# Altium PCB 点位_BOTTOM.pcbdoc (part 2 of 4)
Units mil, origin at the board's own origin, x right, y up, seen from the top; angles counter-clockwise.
Board outline 5102.8 x 4152 mil, 8 copper layers (Top Layer, GND1, 内层2, VCC, 内层4, Inner5, GND2, Bottom Layer); 209 components, 325 nets, 527 pads, 1119 vias.
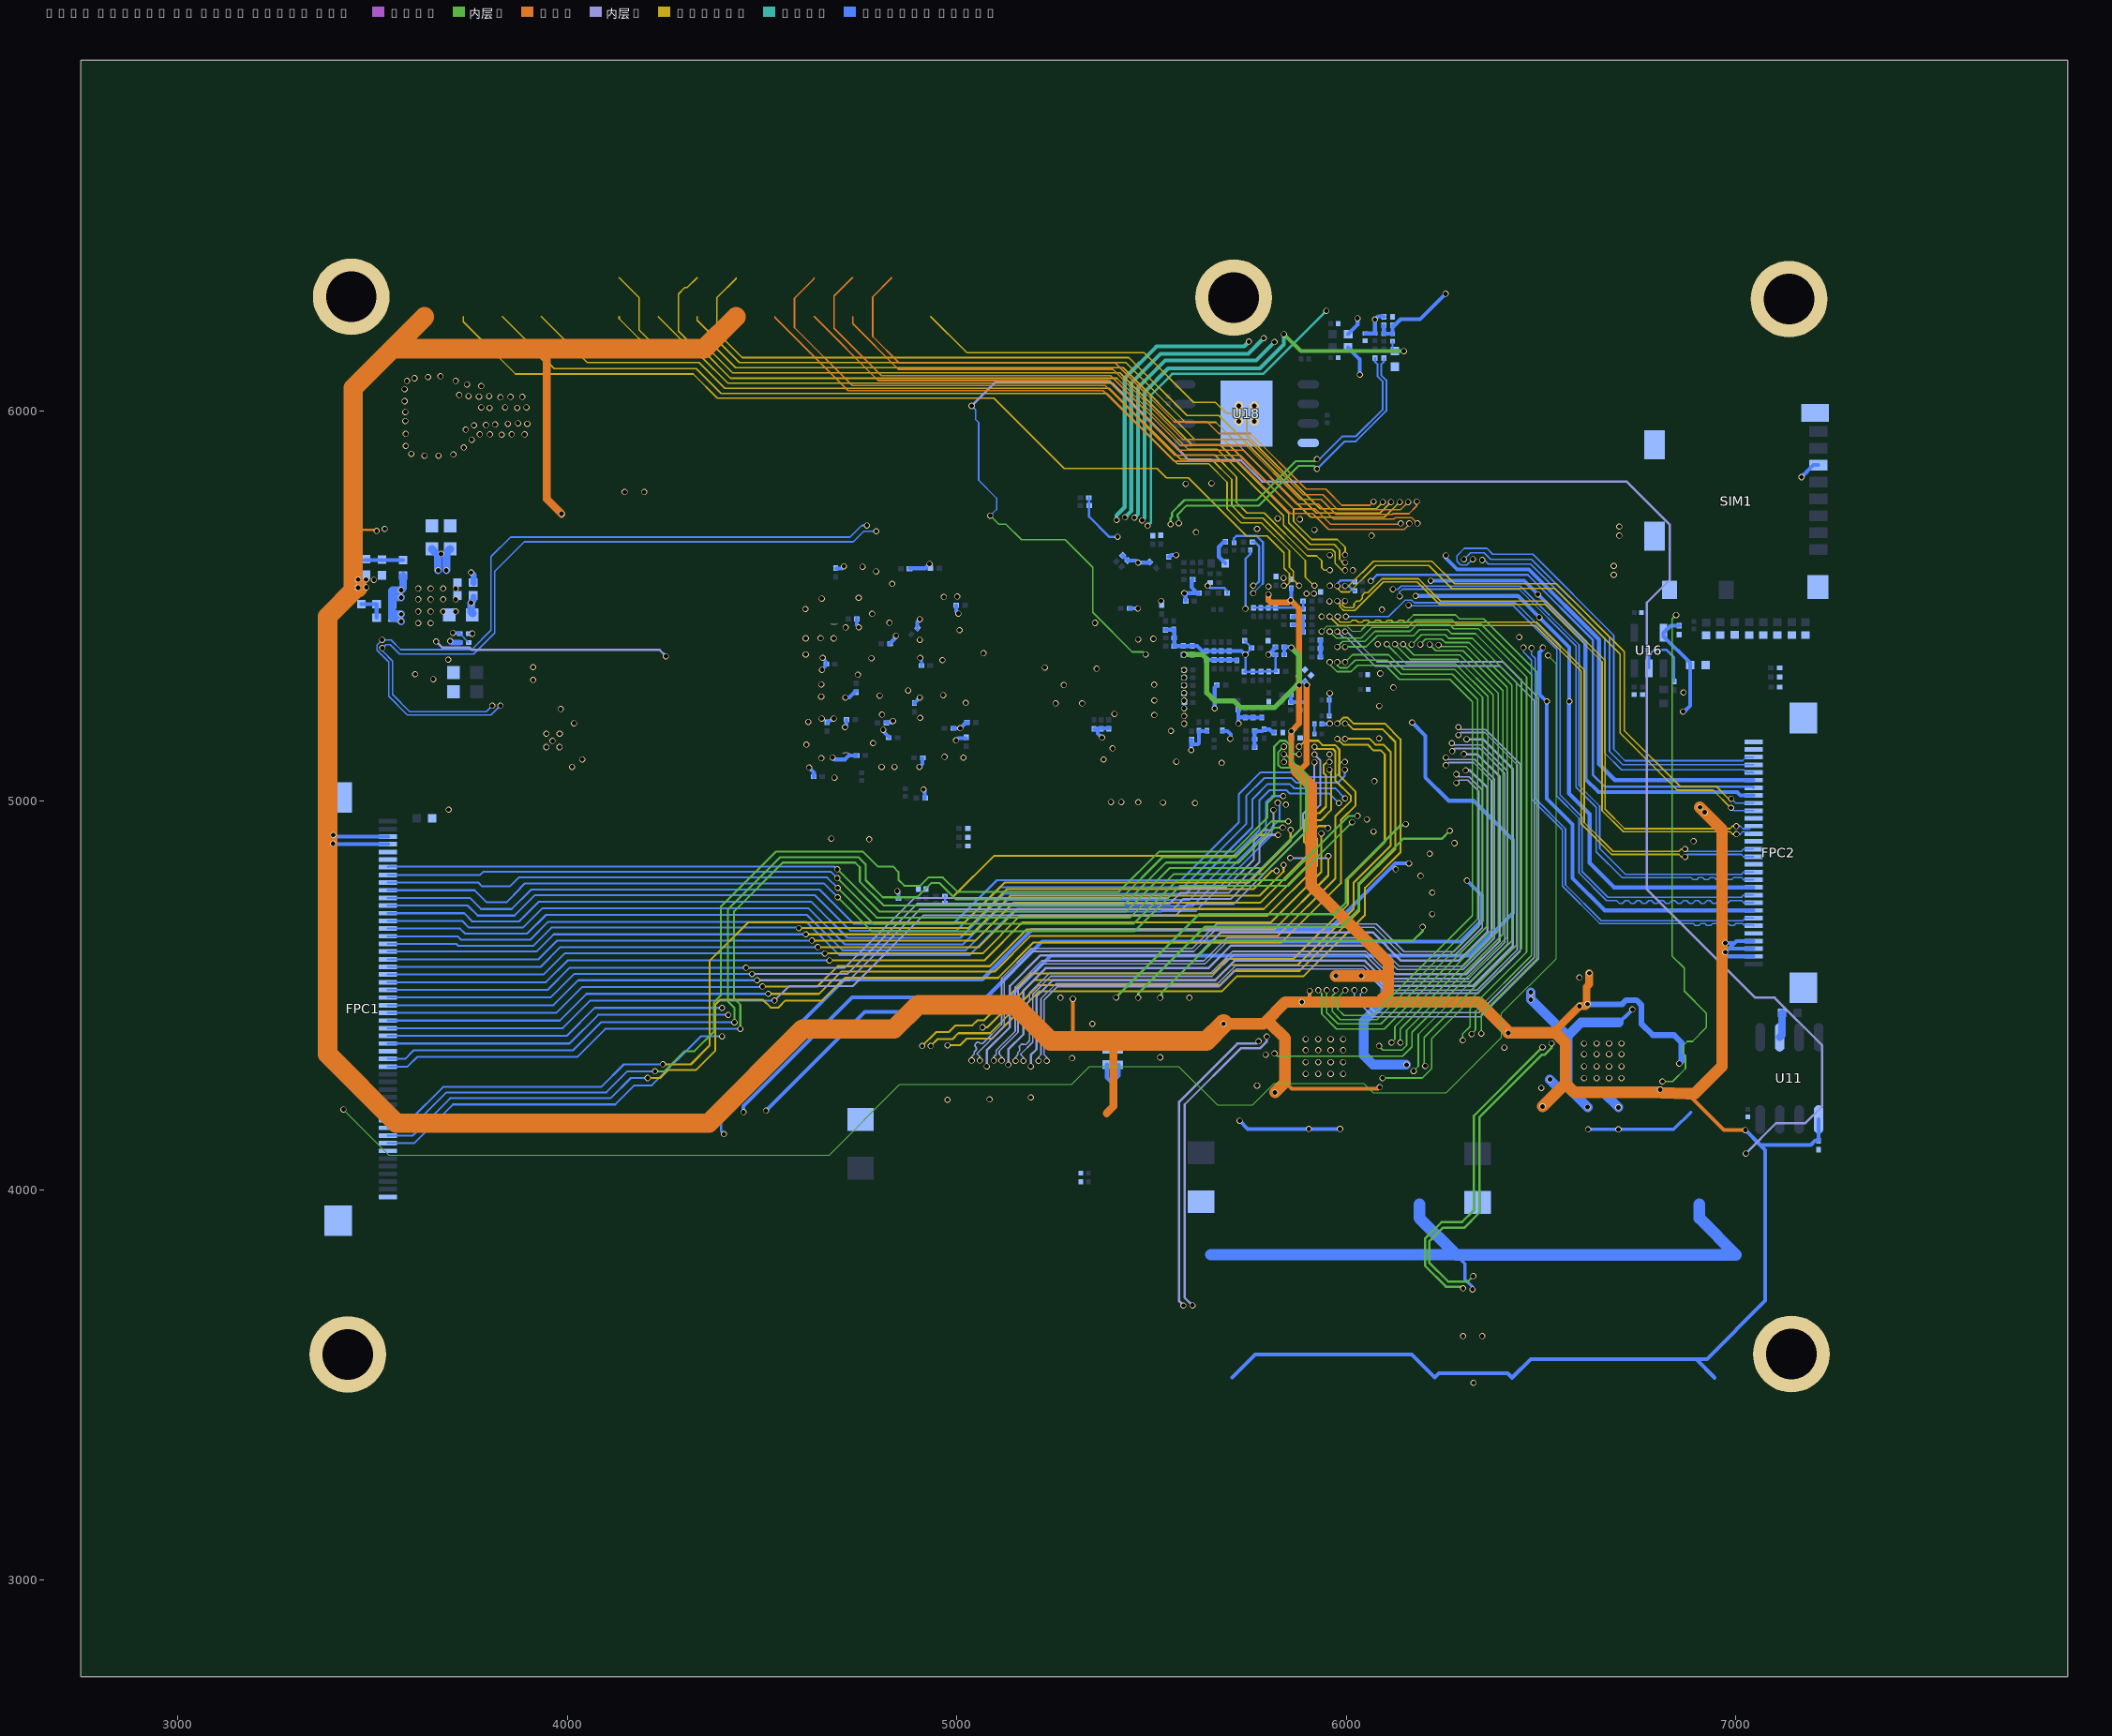
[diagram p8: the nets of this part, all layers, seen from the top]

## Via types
v1: diameter 15.75, hole 11.8, Top Layer to Bottom Layer, 496 vias
v2: diameter 15.7, hole 11.8, Top Layer to Bottom Layer, 335 vias
v3: diameter 15.75, hole 11.81, Top Layer to Bottom Layer, 279 vias
v4: diameter 24, hole 12, Top Layer to Bottom Layer, 9 vias

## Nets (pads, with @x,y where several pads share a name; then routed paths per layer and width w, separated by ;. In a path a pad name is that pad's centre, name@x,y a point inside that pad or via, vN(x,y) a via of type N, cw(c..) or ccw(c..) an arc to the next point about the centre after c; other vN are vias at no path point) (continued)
GM0_LED1:  | length 814.5
  内层4 w6: v2(5604.8,3703.92) 5584.8,3723.92 5584.8,4220 5728.8,4364 5777.8,4364 5795.8,4382 v2(5795.8,4394)
GM0_LED2:  | length 796.1
  内层4 w6: v2(5581.8,3703.69) 5570.8,3714.69 5570.8,4227 5719.8,4376 5768.8,4376 v2(5774.8,4382)
GM1_DVDD10:  | length 736.2
  Bottom Layer w10: 6699.8,4431 ccw(c6156.31,5042.49) v1(6734.8,4464)
  Bottom Layer w25: v1(6473.8,4508) v1(6473.8,4489.39) 6567.8,4395.39 ; v1(6522.8,4284) 6541.8,4265 6567.8,4265 ; v1(6619.8,4213) 6581.8,4251 ; v1(6698.8,4212.42) 6660.22,4251 6581.8,4251 ; 6699.8,4431 6603.41,4431 6567.8,4395.39 ; 6567.8,4265 6567.8,4395.39 ; 6567.8,4265 6581.8,4251
GM1_DVDDRG: C32.1 C34.1 C42.1 C167.2 C168.2 C169.2 C170.2 C173.2 C174.2 C175.2 C176.2 C177.2 C178.2 C200.2 C204.2 C223.2 C224.2 C276.1 FPC1.3 FPC1.4 FPC2.2 FPC2.3 FPC2.4 U11.5 U16.5 | length 15880.7
  内层2 w13: v2(5583.3,5375.16) 5630.64,5375.16 5641.8,5364 5641.8,5277 5662.8,5256 5711.8,5256 5728.8,5239 5814.8,5239 5872.8,5297 v2(5878.8,5297) 5878.8,5373 v2(5858.8,5393)
  VCC w6: 3449.8,5695.88 3506.92,5695.88 v1(3509.8,5693)
  VCC w10: 5297.42,4383 5297.8,4383.38 v2(5297.8,4491) ; 5842.8,4277 5859.8,4260 6081.8,4260 v2(6085.8,4264) ; 5905.69,4483 5905.8,4483.11 v2(5905.8,4511.5) ; v1(6805.8,4258) 6865.8,4258 6875.8,4248 6969.8,4154 v1(7024.8,4154)
  VCC w15: v1(5799.85,5529.95) 5799.85,5514.96 5805.8,5509 5850.8,5509 v2(5856.8,5515) 5878.8,5493 v2(5878.8,5297) 5878.8,5198.22 v1(5858.89,5178.3) 5858.8,5178.22 5858.8,5092 5867.8,5083 ; 5881.8,5079 5897.8,5095 5897.8,5296 v2(5898.8,5297)
  VCC w20: 3912.8,6165 3916.8,6161 3946.8,6131 3946.8,5774.7 v2(3984.8,5736.7) ; 5384.3,4197.4 5401.8,4214.9 5401.8,4379.05 5397.85,4383 ; 6531.1,4404 6531.1,4404.46 v1(6599.22,4472.58) 6614.4,4472.58 v1(6619.31,4477.49) 6616.8,4480 6616.8,4521.72 6623.8,4528.72 v2(6623.8,4557)
  VCC w30: v1(5684.8,4427) 5787.38,4427 5789.71,4429.34 ; v2(5816.8,4251) 5842.8,4277 5842.8,4390 5803.47,4429.34 5789.71,4429.34 ; 5870.8,5078 5909.43,5039.37 5909.43,4782.37 6107.8,4584 6107.8,4538.28 ; v2(5972.8,4550) v2(6038.15,4550) 6096.09,4550 6107.8,4538.28 ; 6092.8,4492 6107.8,4507 6107.8,4538.28 ; v1(6503.8,4215) 6562.8,4274 ; v1@6806.14,4251 6774.8,4251 ; v2(6907.8,4983) v2(6920.55,4970.25) 6964.8,4926 6964.8,4318 6894.8,4248 6875.8,4248 6774.8,4251 ; 5789.71,4429.34 5843.38,4483 v1(5885.8,4483) 5905.69,4483 6339.8,4483 6415.8,4407 v1(6415.8,4404) 6531.1,4404 6537.07,4404 6562.8,4378.26 6562.8,4274 ; 6562.8,4274 6585.8,4251 6774.8,4251
  VCC w50: 3449.8,5552 3449.8,5695.88 3449.8,6060 3550.8,6161 ; v1(3461.8,5547) 3457.84,5547 3383.8,5472.97 3383.8,4349 3560.8,4172 4362.36,4172 4604.36,4414 4838.8,4414 4900.8,4476 5147.8,4476 5240.8,4383 5297.42,4383 5397.85,4383 5640.8,4383 v1(5684.8,4427) ; 3632.8,6243 3550.8,6161 ; 4432.8,6243 4350.8,6161 3916.8,6161 3550.8,6161
  Bottom Layer w10: v2(3397.8,4890) 3399.58,4888.23 FPC1.4@3538.78,4888.23 ; v2(3398.8,4912) 3402.68,4908.12 3538.57,4908.12 FPC1.3@3538.78,4907.91 ; 5384.3,4197.4 5397.8,4210.9 5397.8,4276 ; C224.2@5384.9,4322.16 5384.9,4288.9 5397.8,4276 ; C223.2@5415.92,4322.1 5415.92,4294.11 5397.8,4276 ; 5706.8,3519.16 5765.65,3578 6167.96,3578 6226.8,3519.16 6237.65,3530 6414.2,3530 6425.8,3518.4 6473.4,3566 6898.2,3566 ; C174.2@5840.8,5375 C173.2@5840.8,5395 5856.8,5395 v2(5858.8,5393) ; v2(5856.8,5515) 5858.8,5517 C170.2@5858.8,5546 ; C169.2@5858.8,5161 5858.89,5161.09 v1(5858.89,5178.3) ; C175.2@5877.8,5276 5877.8,5296 v2(5878.8,5297) 5878.02,5297.78 C167.2@5878.02,5320.22 ; C168.2@5893.02,5306.22 5898.8,5300.44 v2(5898.8,5297) C176.2@5898.8,5276 ; C276.1@6854.8,5449.5 6833.06,5449.5 U16.5@6814.71,5431.15 6814.71,5422.09 6882.8,5354 6882.8,5244 6867.8,5229 v2(6864.8,5229) ; 6945.8,3518.4 6898.2,3566 ; v2(6972.8,4635) 6996.8,4635 ; v1(7024.8,4154) 7062.8,4116 ; FPC2.2@7045.83,4600.26 6979.55,4600.26 6970.8,4609 6981.74,4619.94 ; FPC2.3@7045.83,4619.94 6981.74,4619.94 ; FPC2.4@7045.83,4639.62 7001.43,4639.62 6996.8,4635 ; U11.5@7212.8,4181.39 C204.2@7212.8,4126.5 7203.3,4126.5 7192.8,4116 7062.8,4116 ; 6898.2,3566 6925.8,3566 7075.8,3716 7075.8,4103 7062.8,4116 ; 6981.74,4619.94 6996.8,4635
  Bottom Layer w13: C178.2@5581.18,5374.75 5581.44,5375 C177.2@5603.8,5375
  Bottom Layer w15: v1(6619.31,4477.49) 6619.8,4477 6707.8,4477 6718.8,4488 6744.8,4488 6757.8,4475 6757.8,4427 6786.8,4398 6841.8,4398 6860.8,4379 6860.8,4331 v1(6854.8,4325)
  Bottom Layer w25: v2(6038.15,4550) 6039.15,4551 6070.8,4551 ; 6074.8,4550 6099.8,4525 6099.8,4489 6044.8,4434 6044.8,4346 6068.8,4322 v1@6152.88,4322
  other v1: 6154.8,4322 3483.8,5548 3502.8,5567 3461.8,5568 3482.8,5568
  other v2: 6973.08,4611.28
GM1_LED1:  | length 868.4
  内层2 w6: v1(6325.8,3779) 6311.8,3765 6261.8,3765 6212.8,3814 6212.8,3867.95 6247.85,3903 6302.8,3903 6341.8,3942 6341.8,4187 6501.8,4347 6508.8,4347 6526.89,4365.09 v2(6526.89,4376.91)
GM1_LED2:  | length 838.6
  内层2 w6: v1(6299.8,3748) 6295.8,3752 6255.8,3752 6201.8,3806 6201.8,3875 6244.8,3918 6296.8,3918 6327.8,3949 6327.8,4191.02 v2(6503.78,4367)
GND: C13.2 C14.2 C19.2 C20.2 C21.2 C22.2 C23.2 C24.2 C26.2 C29.2 C30.2 C32.2 C34.2 C36.2 C37.2 C38.2 C39.2 C40.2 C41.2 C42.2 C46.2 C47.2 C48.2 C49.2 C50.2 C56.1 C57.2 C58.2 C67.2 C68.2 C75.2 C76.2 C77.2 C78.2 C79.1 C82.1 C83.2 C84.2 C85.2 C86.2 C90.1 C91.1 C92.1 C93.1 C94.1 C102.1 C103.1 C104.1 C105.1 C106.1 C107.1 C112.1 C113.1 C114.1 C115.1 C116.2 C117.2 C118.1 C119.1 C120.1 C121.1 C122.1 C123.1 C124.1 C125.1 C126.1 C127.1 C128.1 C129.1 C130.1 C132.2 C133.1 C134.2 C135.1 C137.1 C138.1 C141.1 C142.2 C143.2 C144.1 C145.1 C151.1 C152.1 C153.1 C154.1 C155.1 C156.1 C161.2 C162.1 C163.1 C164.1 C165.1 C166.1 C167.1 C168.1 C169.1 C170.1 C171.1 C172.1 C173.1 C174.1 C175.1 C176.1 C177.1 C178.1 C181.1 C182.1 C183.1 C184.1 C185.1 C186.1 C187.1 C188.1 C200.1 C201.1 C202.1 C204.1 C208.1 C209.1 C211.1 C213.1 C214.1 C215.1 C216.1 C223.1 C224.1 C225.2 C226.1 C227.1 C228.2 C229.1 C230.1 C231.2 C232.1 C233.1 C234.2 C235.1 C236.1 C237.1 C240.1 C246.1 C247.1 C248.1 C255.1 C276.2 C277.1 C285.1 C286.1 C287.1 C288.1 C289.1 C294.1 D16.2 D17.1 D18.2 D19.1 D20.2 D21.1 D22.2 D23.1 FPC1.5 FPC1.6 FPC1.31 FPC1.39 FPC1.44 FPC1.50 FPC1.51 FPC1.52 FPC2.5 FPC2.8 FPC2.11 FPC2.14 FPC2.17 FPC2.20 FPC2.23 FPC2.25 FPC2.29 FPC2.30 FPC2.31 FPC2.32 pad.54 R28.1 R44.1 R45.2 R46.1 R49.1 R55.1 R56.1 R57.1 R59.1 R67.1 R68.1 R76.2 R115.1 R116.2 R119.1 R122.1 SIM1.6 SIM1.9 SIM1.10 SIM1.12 SIM1.13 SIM1.14 U11.2 U16.2 U18.4 U18.9 | length 26839.9
  GND1 w3: 4676.72,5453.97 4678.72,5451.97 4690.72,5451.97 4692.72,5453.97 ; 4706.72,5121.97 4708.42,5121.97 4709.4,5122.95 4719.76,5122.95 4720.74,5121.97 4724.72,5121.97
  内层2 w6: v2(5408.8,4495) 5622.8,4709 5969.8,4709 5998.8,4738 5998.8,4797 6137.49,4935.68 6148.49,4935.68 v2(6152.8,4940) ; v2(5465.2,4493.87) 5465.2,4504.72 5636.48,4676 5985.8,4676 6031.8,4722 6031.8,4788 6145.8,4902 6244.8,4902 v2(6265.8,4923) ; v2(5521.8,4494) 5524.31,4494 5525.8,4495.49 5525.8,4507 5658.8,4640 6170.65,4640 6195.8,4665.15 v2(6195.8,4676)
  内层4 w6: v1(5076.8,4318) 5076.8,4359 5135.8,4418 5135.8,4524 5214.8,4603 5618.8,4603 5677.8,4662 6067.8,4662 6140.8,4589 6287.8,4589 6361.8,4663 6361.8,5033.87 6317.68,5078 v1(6306.8,5078) ; v2(5131.8,4322) 5131.8,4361 5170.8,4400 5170.8,4513 5227.8,4570 5645.8,4570 5703.8,4628 6051.8,4628 6124.8,4555 6308.8,4555 6393.8,4640 6393.8,5062 6336.8,5119 6302.8,5119 v1(6301.8,5120) ; v1(5189.8,4318) 5189.8,4347 5204.8,4362 5204.8,4498 5245.8,4539 5662.8,4539 5712.8,4589 6047.8,4589 6112.8,4524 6324.8,4524 6426.8,4626 6426.8,5082 6350.8,5158 v1(6308.8,5158)
  Bottom Layer w4: C46.2@3723.8,5429 C30.2@3745.8,5406
  Bottom Layer w6: 4398.8,4229 4394.8,4225 4394.8,4151 v2(4401.8,4144) ; C225.2@4968.8,4736 4969.3,4736.5 C226.1@4969.3,4755 ; C184.1@5339.27,5778.12 5339.58,5777.81 C183.1@5339.58,5758.12 5339.58,5729.23 5390.8,5678 v1(5412.8,5678) ; v2(5643.8,5552) 5649.8,5546 5686.8,5546 5694.3,5538.5 C112.1@5694.3,5533 ; C208.1@5738.8,5411.5 5756.8,5393.5 C47.2@5756.8,5392 5756.8,5391.18 v2(5740.78,5375.16) 5740.78,5333.98 C19.2@5737.8,5331 C24.2@5759.8,5331 5779.8,5331 C50.2@5780.8,5332 C49.2@5800.8,5332 C187.1@5816.96,5332 ; C107.1@5758.3,5664 5765.8,5664 5775.8,5654 5775.8,5563 5765.12,5552.31 v1(5760.88,5552.31) ; C77.2@5761.55,5495.75 C78.2@5780.55,5495.75 C76.2@5799.55,5495.75 C75.2@5818.55,5495.75 5885.55,5495.75 C211.1@5889.3,5492 C213.1@5889.3,5513 ; C174.1@5818.3,5375 5818.3,5333.34 C187.1@5816.96,5332 ; C187.1@5821.3,5332 C187.1@5816.96,5332 ; R55.1@5918.29,5171.53 R59.1@5918.29,5197 ; R46.1@5956.31,5218 R44.1@5956.31,5258.47 5957.33,5259.48 v1(5957.33,5276) ; U16.2@6777.31,5340.31 6777.31,5374.51 6790.8,5388 6821.8,5388 6841.8,5368 C277.1@6841.8,5306.5
  Bottom Layer w8: v2(3705.8,5431) 3721.8,5431 C46.2@3723.8,5429 ; v3(4653.64,5335.97) 4664.22,5346.55 4664.22,5357.89 v3(4655.12,5366.99) ; v3(4905.59,5366.86) 4909.22,5363.23 C121.1@4909.22,5345.97 ; 6282.56,3833.5 6304.8,3811.26 6304.8,3771 6323.8,3752 v1(6323.8,3745) ; v1(6620.8,4156) v1(6698.8,4156) 6840.8,4156 6884.8,4200
  Bottom Layer w10: C42.2@3470.8,5504.99 3509.53,5504.99 C29.2@3509.81,5504.72 C79.1@3509.81,5470 ; C34.2@3479.01,5618.33 3479.33,5618.01 3511.8,5618.01 3542.8,5618.01 C26.2@3577.8,5618.01 ; 4398.8,4229 4710.8,4541 5064.8,4541 5191.8,4668 5954.8,4668 6125.8,4839 v1(6160.8,4839) ; v2@4451.8,4204 4451.8,4216 4730.8,4495 5075.8,4495 5218.8,4638 6293.8,4638 6348.8,4693 6348.8,4756 v2(6309.8,4795) ; v2(4509.8,4204) 4763.8,4458 5096.8,4458 5240.8,4602 6317.8,4602 6427.8,4712 6427.8,4899 6326.8,5000 6262.8,5000 6202.8,5060 6202.8,5167 v2(6168.8,5201) ; v3(4620.57,5084.95) 4632.62,5072.9 C116.2@4632.62,5060.67 ; C117.2@4666.8,5201 v3(4683.78,5211.02) ; v3(4680.72,5110.97) 4685.72,5105.97 4712.72,5105.97 4722.72,5115.97 C124.1@4742.88,5115.97 ; C143.2@4689.72,5596.47 4704.22,5596.47 v3(4709.72,5601.97) ; v3(4712.72,5188.97) 4716.22,5192.47 C137.1@4716.22,5207.97 ; v3(4713.71,5265.01) 4723.75,5265.01 4739.87,5281.13 C142.2@4741.72,5281.13 ; C130.1@4742.6,5467.31 4742.6,5450.77 v3(4748.05,5445.32) ; v3(4810.72,5181.97) 4810.72,5178.47 C135.1@4826.22,5162.97 ; C151.1@4817.56,5200.97 4831.64,5200.97 v3(4835.64,5204.97) ; C120.1@4826.6,5402.68 4843.9,5419.98 v3(4843.9,5423.94) ; v2(4846.8,4768) 4850.3,4764.5 C230.1@4850.3,4749 ; C144.1@4877.56,5596.97 4918.72,5596.97 v3(4929.72,5607.97) ; C134.2@4891.72,5249.81 4891.72,5251.97 v3(4904.72,5264.97) ; C141.1@4897.88,5440.97 4897.88,5459.13 v3(4904.72,5465.97) ; v3(4903.72,5086.97) 4911.22,5094.47 C118.1@4911.22,5109.97 ; v3(4914.08,5028.72) 4917.74,5025.06 4917.74,5007.06 C152.1@4916.74,5006.06 ; C138.1@4990.22,5186.97 4991.22,5185.97 v3(5008.72,5185.97) 5023.72,5200.97 C122.1@5027.88,5200.97 ; C145.1@4997.88,5500.97 4997.88,5486.33 v3(5003.72,5480.49) ; v3(4998.02,5154.7) 5004.13,5160.81 C123.1@5022.72,5160.81 ; C162.1@5353.72,5183.97 5355.57,5183.97 5361.72,5177.83 ; v3(5372.72,5161.97) 5361.72,5172.97 5361.72,5177.83 ; C132.2@5391.72,5187.13 5390.72,5186.13 5361.72,5186.13 5361.72,5177.83 ; C181.1@5425.29,5630.17 C182.1@5438.73,5616.74 5459.83,5616.74 v2(5465.2,5611.37) 5493.91,5611.37 C202.1@5495.67,5613.13 ; C94.1@5443.3,5494 v2(5464.8,5494) ; C13.2@5535.45,5439.18 5556.32,5439.18 C14.2@5556.49,5439.35 5558.3,5437.54 C90.1@5558.3,5418 C93.1@5558.3,5397 5600.68,5397 5601.06,5397.38 5617.08,5397.38 5629.65,5384.81 C84.2@5641.03,5384.81 C83.2@5660.03,5384.81 C86.2@5699.03,5384.81 5731.13,5384.81 v2(5740.78,5375.16) ; C172.1@5543.8,5626.5 5545.45,5626.5 5549.95,5631 v2(5562.8,5631) ; C102.1@5587.3,5513 5587.3,5529.5 v2(5583.8,5533) C113.1@5617.8,5533 ; v3(5601.72,5129.97) 5601.72,5142.47 ; C133.1@5602.8,5156.5 5601.72,5155.42 5601.72,5142.47 ; C103.1@5605.3,5568 5602.8,5565.5 5602.8,5548 C113.1@5617.8,5533 ; C113.1@5621.3,5533 C113.1@5617.8,5533 ; C40.2@5640.8,5362 5717.88,5362 C39.2@5718.91,5360.97 ; C119.1@5642.72,5178.47 5621.72,5178.47 5621.72,5147.97 5618.72,5144.97 5604.22,5144.97 5601.72,5142.47 ; v2(5661.8,5237) 5661.8,5291 C41.2@5667.8,5297 ; C129.1@5681.72,5178.47 5695.22,5178.47 5703.72,5169.97 5703.72,5160.97 v3(5701.72,5158.97) ; R28.1@5688.8,5610 5672.8,5626 5672.8,5652 5685.3,5664.5 C106.1@5689.8,5664.5 ; C20.2@5721.8,5234 5722.8,5233 5722.8,5214.13 ; v2(5722.8,5198) 5722.8,5214.13 ; v1(5725.8,4178) 5746.8,4157 v1(5903.8,4157) v1(5983.8,4157) ; C227.1@5764.3,5137 C163.1@5764.3,5158 C164.1@5764.3,5179 5784.3,5179 C91.1@5788.8,5183.5 5789.5,5182.8 5803.64,5182.8 5810.95,5175.5 C166.1@5814.8,5175.5 ; C21.2@5782.8,5214 C22.2@5760.8,5214 5760.67,5214.13 5722.8,5214.13 ; C174.1@5818.3,5375 5818.15,5375.16 v2(5799.84,5375.16) 5818.3,5393.62 C173.1@5818.3,5395 ; C186.1@5857.3,5272 C185.1@5857.3,5253 C175.1@5878.3,5253 ; C104.1@5862.3,5452 C215.1@5888.8,5452 ; C188.1@5862.3,5473 5887.8,5473 C216.1@5888.8,5472 C215.1@5888.8,5452 ; C175.1@5877.8,5253.5 C175.1@5878.3,5253 ; C201.1@5880.3,5233 5880.3,5251 C175.1@5878.3,5253 ; C68.2@5888.8,5433 C215.1@5888.8,5452 ; C176.1@5898.8,5253.5 5898.3,5253 C175.1@5878.3,5253 ; C58.2@5933.8,5369 C57.2@5933.8,5391 C67.2@5933.8,5413 ; v2(6177.8,5526) 6440.8,5526 v2(6495.8,5471) 6572.8,5394 v2(6572.8,5255) 6571.8,5254 6571.8,5019 6624.8,4966 6624.8,4840 6687.39,4777.41 FPC2.11@7045.83,4777.41 ; v2(6216.8,5565) 6456.8,5565 v2(6491.8,5530) 6613.8,5408 6613.8,5056 6647.8,5022 7003.8,5022 7012.17,5013.64 FPC2.23@7045.83,5013.64 ; v2(6255.8,5630) 6255.8,5623 6284.8,5594 6468.8,5594 6648.8,5414 6648.8,5094 6689.8,5053.01 FPC2.25@7045.83,5053.01 ; v2(6504.8,5393) 6504.8,5390 6495.8,5381 6495.8,5274 v2(6514.8,5255) 6514.8,5005 6580.8,4939 6580.8,4801 6663.44,4718.36 FPC2.8@7045.83,4718.36 ; v1(7168.8,5831) 7199.82,5862.02 SIM1.6@7211.94,5862.02
  Bottom Layer w20: U11.2@7112.8,4392.61 7118.8,4398.6 C246.1@7118.8,4455.28
  Bottom Layer w30: 5651.8,3834.26 6281.8,3834.26 ; 6187.7,3964.16 6187.7,3928.36 6281.8,3834.26 ; 6906.7,3963.4 6906.7,3927.6 7000.8,3833.5 6282.56,3833.5 6281.8,3834.26
  other v1: 6326.8,3505 6299.8,3625 6348.8,3625 5083.8,4233 5189.8,4238 5295.81,4339 5521.8,4341 5521.8,4341 5792.8,4348 5347.8,4427 5844.8,4990 6071.8,5050 5839.52,5099.56 5956.8,5119 3945.89,5137.74 3979.71,5137.74 3961.64,5153.49 6083.8,5160 3945.8,5172 3979.8,5172 5583.3,5197.99 5583.3,5217.68 5583.3,5237.36 6084.68,5243.47 5583.3,5257.03 5583.3,5276.73 6120.8,5291 5583.3,5296.4 3655.09,5312 5583.3,5316.1 3608.8,5325 6087.22,5326.69 5583.3,5335.78 3693.55,5362.22 6080.8,5402 5465.2,5414.53 5504.56,5415.76 5354.8,5456.76 6091.55,5490.65 5799.8,5550 5957.8,5552 5838.8,5572 6686.8,5580 6016.8,5592 6686.8,5603 5957.8,5631 6064.8,5681 6700.8,5681 5614.23,5689.43 5917.8,5696 5770.8,5698 6700.8,5704 5880.45,5722.74 5823.8,5725 5587.8,5814 5653.8,5815
  other v2: 4451.8,4200.58 4975.8,4232 6500.8,4262.5 5770.8,4268.47 6610.71,4287.95 6642.71,4287.95 6674.71,4287.95 6706.71,4287.95 5895.8,4298.5 5927.8,4298.5 5959.8,4298.5 5991.8,4298.5 6610.71,4317.95 6642.71,4317.95 6674.71,4317.95 6706.71,4317.95 5895.8,4328.5 5927.8,4328.5 5959.8,4328.5 5991.8,4328.5 6610.71,4348.95 6642.71,4348.95 6674.71,4348.95 6706.71,4348.95 5895.8,4359.5 5927.8,4359.5 5959.8,4359.5 5991.8,4359.5 6405.8,4366 6610.71,4376.95 6642.71,4376.95 6674.71,4376.95 6706.71,4376.95 5895.8,4387.5 5927.8,4387.5 5959.8,4387.5 5991.8,4387.5 5265.8,4494 5596.8,4494 6598.8,4546 6220.8,4709 6220.8,4764 6190.8,4807 6126.8,4824 6213.8,4864 6277.8,4891 6891.8,4896 4774.8,4901 4677.8,4903 6069.8,4921 6052.8,4952 3694.8,4977 4011.8,5087 6865.8,5278 3911.8,5310.28 3911.8,5343 6443.8,5420 3616.8,5456 3648.8,5456 5936.8,5473 3616.8,5486 3648.8,5486 3680.8,5486 3712.8,5486 5956.8,5512 5524.25,5512.95 3616.8,5517 3648.8,5517 3680.8,5517 3712.8,5517 5897.8,5532 5916.8,5532 3616.8,5545 3648.8,5545 3680.8,5545 3712.8,5545 3530.8,5698 4146.85,5793 4196.8,5793 3632.8,5886 3668.8,5886 3706.8,5889 3598.8,5891 3733.8,5907 3584.8,5911 3753.8,5927 3830.8,5940 3774.8,5941 3800.8,5941 3856.8,5941 3889.8,5941 3584.8,5942 3738.8,5953 3759.8,5964 3790.8,5965 3813.8,5966 3846.8,5968 3896.8,5968 3872.8,5969 3583.8,5975 3583.8,5998 3799.8,6009 3870.8,6009 3778.8,6010 3839.8,6010 3894.8,6010 3581.8,6026 3827.8,6036 3853.8,6037 3883.8,6037 3772.8,6038 3745.8,6039 3798.8,6039 3721.8,6042 3581.8,6057 3778.8,6065 3741.8,6069 3587.8,6078 3712.8,6078 3606.8,6085 3641.8,6088 3673.8,6090
  other v3: 5611.72,4993.97 5465.72,4995.97 5529.24,4995.51 5395.41,4996.51 5421.96,4996.51 4685.37,5059.21 4806.72,5086.97 4839.72,5086.97 5680.01,5097.25 5563.72,5099.97 5376.72,5105.97 4651.72,5108.97 5016.72,5110.64 4968.09,5112.71 5399.97,5134.47 4613.64,5143.97 4784.72,5147.97 5549.72,5179.22 4618.33,5202.59 4653.07,5210.76 4905.72,5212.97 5506.8,5220 4807.72,5220.97 5404.72,5222.97 5253.72,5249.97 5321.72,5249.97 5022.72,5251.22 5506.77,5257.46 4651.48,5267.64 4801.72,5269.97 4964.8,5271 4874.72,5282.97 5274.72,5296.72 5506.56,5298.24 4651.64,5298.97 4745.71,5323.56 5358.8,5339 5225.72,5341.97 4962.72,5360.97 4780.72,5365.97 4611.72,5375.97 5068.3,5378.72 4904.72,5413.15 4611.72,5416.97 4650.01,5417.22 4683.72,5416.97 5006.8,5438.05 4714.52,5444.96 4826.72,5456.97 4782.2,5479.83 4610.67,5492.24 4653.1,5519.11 4747.72,5521.01 4966.64,5522.97 5000.98,5524.33 4833.72,5556.97 4792.72,5588.97 4757.72,5600.97
  other v4: 5724.12,5974.31 5763.49,5974.31 5724.12,6013.68 5763.49,6013.68
HBIAS: C237.2 R64.2 | length 1143.7
  内层2 w10: v1(5839.8,6198) 5883.31,6154.49 v1(6147.8,6154.49)
  GND2 w10: v1(5475.8,5720) 5481.8,5726 5481.8,6049 5542.8,6110 5777.8,6110 5839.8,6172 v1(5839.8,6198)
  Bottom Layer w5: R64.2@6118.57,6179.98 6118.57,6160.49 C237.2@6124.57,6154.49 v1(6147.8,6154.49)
HCEC:  | length 1807
  Inner5 w5: v1(4910.8,4370) 4946.8,4406 4979.8,4406 4996.8,4423 5039.8,4423 5052.8,4436 5069.8,4436 5189.8,4556 5656.8,4556 5694.8,4594 5864.8,4594 6003.8,4733 6003.8,4798 6098.8,4893 6098.8,5119 6088.8,5129 6069.8,5129 6054.8,5144 5991.94,5144 v1(5977.01,5158.93)
HHPD:  | length 1652.4
  Inner5 w5: v1(5065.8,4418) 5077.8,4418 5199.8,4540 5664.8,4540 5702.8,4578 5874.8,4578 6018.8,4722 6018.8,4789 6113.8,4884 6113.8,5125 6094.8,5144 6074.8,5144 6059.87,5158.93 v1(5996.69,5158.93)
HP-DET:  | length 879.2
  GND2 w6: v1(5489.8,5706) 5497.8,5714 5497.8,6041 5552.8,6096 5786.8,6096 v1(5948.8,6258)
HPOUTFB: C239.1 R66.2 R122.2 | length 826.9
  GND2 w10: v1(5431.8,5728) 5447.8,5744 5447.8,6073 5522.8,6148 5747.8,6148 v1(5787.8,6188)
  Bottom Layer w10: R122.2@6048.57,6200 R66.2@6073.57,6200 v1(6073.57,6235.76) 6081.8,6244 6095.55,6244 C239.1@6096.57,6242.99
HPOUTL: C243.1 | length 788.1
  GND2 w10: v1(5455.8,5727) 5464.8,5736 5464.8,6061 5534.8,6131 5768.8,6131 v1(5815.8,6178)
  Bottom Layer w10: C243.1@6004.8,6198 6028.8,6222.01 v1(6028.8,6239)
HPOUTR: C242.1 | length 813
  GND2 w10: v1(5409.8,5721) 5409.8,5733 5430.8,5754 5430.8,6085 5512.8,6167 5737.8,6167 v1(5749.8,6179)
  Bottom Layer w10: C242.1@6004.52,6163.85 6034.8,6133.57 v1(6034.8,6094)
HREXT: R59.2 | length 20.6
  Bottom Layer w10: R59.2@5937.31,5197 5956.03,5197 v1(5957.33,5198.3)
HS-MIC: C239.2 C240.2 R64.1 R65.2 | length 235.1
  Bottom Layer w5: R65.2@6096.57,6199.49 R65.2@6096.99,6199.06
  Bottom Layer w10: R65.2@6096.57,6199 6096.57,6199.49 C239.2@6096.57,6220.49 ; R65.2@6096.99,6199.06 R64.1@6118.5,6199.06 ; R64.1@6118.57,6199 C240.2@6118.57,6220.49 6123.29,6220.49 6139.8,6237 6189.8,6237 v1(6254.8,6302)
HSCL:  | length 1865.5
  Inner5 w5: v1(4932.8,4370) 4950.8,4388 4988.8,4388 5003.8,4403 5085.8,4403 5208.8,4526 5673.8,4526 5710.8,4563 5879.8,4563 6032.8,4716 6032.8,4783 6125.8,4876 6125.8,5151 6093.8,5183 6017.8,5183 6002.5,5198.3 v1(5996.69,5198.3)
HSDA:  | length 1891
  Inner5 w5: v1(4975.8,4372) 5007.8,4372 5024.8,4389 5089.8,4389 5211.8,4511 5680.8,4511 5718.8,4549 5889.8,4549 6047.8,4707 6047.8,4776 6138.8,4867 6138.8,5158 6098.51,5198.3 6018.51,5198.3 6002.8,5214 5992.7,5214 v1(5977,5198.3)
HTX0N:  | length 2088.5
  内层4 w4: v1(5094.8,4333) 5094.8,4342.87 5100.8,4348.87 5100.8,4358.99 5149.8,4408 5149.8,4521.34 5217.48,4589.02 5633.82,4589.02 5692.82,4648.02 6062.79,4648.02 6136.14,4574.67 6296.47,4574.67 6372.8,4651 6372.8,5052 6326.8,5098 6262.8,5098 v1(6255.8,5091)
HTX0P:  | length 2101
  内层4 w4: v1(5114.8,4333) 5114.8,4342.87 5108.81,4348.87 5108.81,4357.11 5156.8,4405.1 5156.8,4517 5220.8,4581 5637.14,4581 5696.14,4640 6057.8,4640 6131.15,4566.65 6299.79,4566.65 6380.8,4647.66 6380.8,5055.34 6330.12,5106.02 6260.79,5106.02 v1(6255.8,5111)
HTX1N:  | length 2140
  内层4 w4: v1(5150.8,4332) 5150.8,4341.87 5156.3,4347.37 5156.3,4353.02 5161.07,4357.8 5161.07,4363.46 5160.49,4364.03 5160.49,4369.69 5165.44,4374.64 5171.1,4374.64 5171.68,4374.06 5177.33,4374.06 5186.79,4383.52 5186.79,4406.66 5181.79,4411.66 5181.79,4421.66 5186.79,4426.66 5186.79,4436.66 5181.79,4441.66 5181.79,4451.66 5186.79,4456.66 5186.79,4466.66 5181.79,4471.66 5181.79,4481.66 5186.79,4486.66 5186.79,4506.32 5237.48,4557.02 5651.82,4557.02 5707.8,4613 6050.79,4613.02 6120.8,4543 6313.8,4543 6406.8,4636 6406.8,5070 6342.8,5134 6278.8,5134 v1(6271.8,5127)
HTX1P:  | length 2133.8
  内层4 w4: v1(5170.8,4332) 5170.8,4340.87 5164.31,4347.37 5164.31,4349.37 5194.8,4379.86 5194.8,4503 5240.8,4549 5655.14,4549 5711.14,4605 6046.8,4605 6116.82,4534.98 6317.12,4534.98 6413.8,4631.66 6413.8,5076 6346.8,5143 6275.8,5143 v1(6270.8,5148)
HTX2N:  | length 2151.2
  内层4 w4: v1(5209.8,4332) 5209.8,4341.87 5216.13,4348.2 5216.13,4491.66 5254.48,4530.02 5669.48,4530.02 5715.47,4576 ; 5715.48,4576.02 6046.1,4576.02 6108.12,4514 6335.8,4514 6438.8,4617 6438.8,5092.1 6355.9,5175 6293.8,5175 v1(6287.8,5169)
HTX2P:  | length 2163.6
  内层4 w4: v1(5230.47,4332) 5230.47,4341.87 5224.14,4348.2 5224.14,4488.34 5257.8,4522 5672.8,4522 5718.8,4568 6042.8,4568 6104.82,4505.98 6339.12,4505.98 6446.82,4613.68 6446.82,5093.98 6357.8,5183 6293.8,5183 v1(6287.8,5189)
HTXCN:  | length 2017.3
  内层4 w4: v1(5037.8,4333) 5037.8,4342.87 5044.3,4349.37 5044.3,4354.69 5048.16,4358.56 ccw(c5043.71,4363.01) 5048.16,4367.46 cw(c5052.62,4371.91) 5048.16,4376.36 5049.87,4378.07 cw(c5054.32,4373.61) 5058.77,4378.07 ccw(c5063.22,4382.52) 5067.67,4378.07 5114.8,4425.19 5114.8,4544.34 5191.48,4621.02 5604.82,4621.02 5666.82,4683.02 6076.79,4683.02 6147.8,4612 6275.8,4612 6340.8,4677 6340.8,5024 6311.8,5053 6289.8,5053 v1(6282.8,5046)
HTXCP:  | length 2016.2
  内层4 w4: v1(5058.8,4333) 5058.8,4342.87 5052.31,4349.37 5052.31,4351.37 5121.8,4420.86 5121.8,4540 5194.8,4613 5608.14,4613 5670.14,4675 6071.8,4675 6142.82,4603.98 6279.12,4603.98 6348.82,4673.68 6348.82,5027.32 6315.14,5061 6289.8,5061 v1(6282.8,5068)
IR-RX:  | length 4880.4
  内层2 w4: v2(5085.8,5732) 5107.8,5710 5125.8,5710 5165.8,5670 5277.8,5670 5348.8,5599 5348.8,5483.58 5450.38,5382 5478.8,5382 v2(5484.8,5376)
  内层4 w6: v2(5037.8,6014) 5100.8,6077 5392.8,6077 5594.8,5875 5728.8,5875 5783.8,5820 6718.8,5820 6830.8,5708 6830.8,5568 6771.8,5509 6771.8,4772 7049.8,4494 7099.8,4494 7221.8,4372 7221.8,4215 7178.8,4172 7103.8,4172 v2(7025.8,4094)
  Bottom Layer w4: v2(5037.8,6014) 5047.8,6004 5047.8,5979 5055.8,5971 5055.8,5823 5101.8,5777 5101.8,5748 v2(5085.8,5732)
LCD0-CLK: FPC1.43 | length 971.7
  Bottom Layer w5: FPC1.43@3538.78,4120.52 3606.32,4120.52 3705.8,4220 4122.8,4220 4171.8,4269 4216.8,4269 4342.8,4395 v1(4396.8,4395)
LCD0-D0: FPC1.7 | length 2737.5
  内层2 w5: v1(4692.8,4824) 4801.8,4715 5433.8,4715 5545.8,4827 5781.8,4827 5882.8,4928 5882.8,5060 5857.8,5085 5831.8,5085 5824.8,5092 5824.8,5124.22 v1(5839.52,5138.93)
  Bottom Layer w5: FPC1.7@3538.78,4829.18 3540.78,4831.18 4685.63,4831.18 v1(4692.8,4824)
LCD0-D1: FPC1.8 | length 2726.6
  内层2 w5: v1(4692.8,4801) 4793.8,4700 5444.8,4700 5556.8,4812 5786.8,4812 5897.8,4923 5897.8,5065 5843.56,5119.25 v1(5839.52,5119.25)
  Bottom Layer w5: FPC1.8@3538.78,4809.48 3775.48,4809.48 3784,4818 4675.8,4818 v1(4692.8,4801)
LCD0-D2: FPC1.9 | length 2667.6
  内层2 w5: v1(4693.8,4776) 4785.8,4684 5453.8,4684 5565.8,4796 5841.8,4796 6006.8,4961 v1(6028.8,4961)
  Bottom Layer w5: FPC1.9@3538.78,4789.81 3771,4789.81 3780.8,4780 3851.8,4780 3874.8,4803 4666.8,4803 v1(4693.8,4776)
LCD0-D3: FPC1.10 | length 2676.7
  内层2 w5: v1(4693.8,4752) 4780.8,4665 5456.8,4665 5572.8,4781 5850.8,4781 v1(6014.8,4945)
  Bottom Layer w5: FPC1.10@3538.78,4770.11 3761.69,4770.11 3792.8,4739 3842.8,4739 3878.8,4775 3878.8,4776 3890.8,4788 4657.8,4788 v1(4693.8,4752)
LCD0-D4: FPC1.11 | length 2763.8
  Bottom Layer w5: FPC1.11@3538.78,4750.44 3749.37,4750.44 3777.8,4722 3856.8,4722 3906.8,4772 4646.8,4772 4734.8,4684 4990.8,4684 5102.8,4796 5574.8,4796 5723.8,4945 5723.8,5017 5779.8,5073 5864.8,5073 5876.8,5061 5972.12,5061 5981.8,5070.68 5981.8,5093.57 5987.79,5099.56 v1(5996.01,5099.56)
LCD0-D5: FPC1.12 | length 2759.9
  Bottom Layer w5: FPC1.12@3538.78,4730.74 3744.06,4730.74 3769.8,4705 3863.8,4705 3915.8,4757 4635.8,4757 4726.8,4666 4998.8,4666 5110.8,4778 5580.8,4778 5742.8,4940 5742.8,5012 5788.8,5058 5859.8,5058 5871.8,5046 5977.8,5046 5996,5064.2 v1(5996,5079.88)
LCD0-D6: FPC1.13 | length 2747.5
  Bottom Layer w5: FPC1.13@3538.78,4711.06 3734.74,4711.06 3755.8,4690 3875.8,4690 3926.8,4741 4625.8,4741 4718.8,4648 5008.8,4648 5121.8,4761 5587.8,4761 5758.8,4932 5758.8,5004 5797.8,5043 5854.8,5043 5865.8,5032 5970.8,5032 v1(5996.8,5006)
LCD0-D7: FPC1.14 | length 2730.7
  Bottom Layer w5: FPC1.14@3538.78,4691.38 3729.43,4691.38 3746.8,4674 3885.8,4674 3935.8,4724 4618.8,4724 4711.8,4631 5015.8,4631 5129.8,4745 5596.8,4745 5776.8,4925 5776.8,5001 5802.8,5027 5845.8,5027 5853.8,5019 5955.8,5019 v1(5980.8,4994)
LCD0-D8: FPC1.15 | length 2571.6
  Bottom Layer w5: FPC1.15@3538.78,4671.69 3724.11,4671.69 3736.8,4659 3896.8,4659 3944.8,4707 4614.8,4707 4705.8,4616 5022.8,4616 5136.8,4730 5605.8,4730 5793.8,4918 5793.8,4996 5809.8,5012 v1(5837.8,5012)
LCD0-D9: FPC1.16 | length 2549.8
  Bottom Layer w5: FPC1.16@3538.78,4652.01 3717.8,4652.01 3726.8,4643 3904.8,4643 3950.8,4689 4612.8,4689 4698.8,4603 5031.8,4603 5143.8,4715 5524.8,4715 5526.8,4717 5613.8,4717 5807.8,4911 5807.8,4931 5828.8,4952 5828.8,4990 v1(5823.8,4995)
LCD0-D10: FPC1.17 | length 2365
  Inner5 w5: v1(4593.8,4673) 5028.8,4673 5128.8,4773 5761.8,4773 5808.8,4820 v1(5820.8,4820)
  Bottom Layer w5: FPC1.17@3538.78,4632.32 3714.48,4632.32 3719.8,4627 3911.8,4627 3958.8,4674 4592.8,4674 v1(4593.8,4673)
LCD0-D11: FPC1.18 | length 2402.1
  Inner5 w5: v1(4611.8,4657) 5037.8,4657 5136.8,4756 5776.8,4756 5838.8,4818 v1(5838.8,4835)
  Bottom Layer w5: FPC1.18@3538.78,4612.64 3920.44,4612.64 3964.8,4657 v1(4611.8,4657)
LCD0-D12: FPC1.19 | length 2763.1
  Inner5 w5: v1(4627.8,4641) 5047.8,4641 5144.8,4738 5778.8,4738 5900.8,4860 5900.8,4885 5891.8,4894 5891.8,4949 5910.8,4968 5930.8,4968 5947.8,4985 5947.8,5065 5941.8,5071 5941.8,5091 5950.36,5099.56 v1(5956.63,5099.56)
  Bottom Layer w5: FPC1.19@3538.78,4592.95 3925.76,4592.95 3973.8,4641 v1(4627.8,4641)
LCD0-D13: FPC1.20 | length 2758.1
  Inner5 w5: v1(4642.8,4624) 5056.8,4624 5154.8,4722 5787.8,4722 5913.8,4848 5913.8,4893 5904.8,4902 5904.8,4935 5919.8,4950 5934.8,4950 5960.8,4976 5960.8,5075.71 v1(5956.63,5079.87)
  Bottom Layer w5: FPC1.20@3538.78,4573.27 3931.07,4573.27 3981.8,4624 v1(4642.8,4624)
LCD0-D14: FPC1.21 | length 2637.3
  Inner5 w5: v1(4660.8,4608) 5065.8,4608 5162.8,4705 5796.8,4705 5924.8,4833 5924.8,4902 5917.8,4909 5917.8,4924 5928.8,4935 5947.8,4935 v1(5952.8,4930)
  Bottom Layer w5: FPC1.21@3538.78,4553.59 3938.39,4553.59 3992.8,4608 v1(4660.8,4608)
LCD0-D15: FPC1.22 | length 2613.3
  Inner5 w5: v1(4672.8,4590) 5070.8,4590 5168.8,4688 5806.8,4688 5935.8,4817 v1(5935.8,4916)
  Bottom Layer w5: FPC1.22@3538.78,4533.9 3944.7,4533.9 4000.8,4590 v1(4672.8,4590)
LCD0-D16: FPC1.23 | length 2521.5
  内层4 w5: v1(4458.8,4571) 4711.8,4571 4890.8,4750 5541.8,4750 5568.8,4777 5690.8,4777 5762.8,4849 5762.8,4898 5789.8,4925 5808.8,4925 5812.8,4929 v1(5812.8,4976)
  Bottom Layer w5: FPC1.23@3538.78,4514.22 3949.02,4514.22 4005.8,4571 v1(4458.8,4571)
LCD0-D17: FPC1.24 | length 3385.3
  内层4 w5: v1(4473.8,4555) 4717.8,4555 4898.8,4736 5546.8,4736 5573.8,4763 5697.8,4763 5776.8,4842 5776.8,4888 5800.8,4912 v1(5824.8,4912)
  Inner5 w5: 4990.8,4754 5095.8,4859 5716.8,4859 5769.8,4912 v1(5824.8,4912)
  Bottom Layer w5: FPC1.24@3538.78,4494.52 3956.33,4494.52 4016.8,4555 v1(4473.8,4555)
LCD0-D18: FPC1.25 | length 2717.8
  内层4 w5: v1(4486.8,4539) 4722.8,4539 4904.8,4721 5554.8,4721 5581.8,4748 5703.8,4748 5888.8,4933 5888.8,4966 5917.8,4995 v1(5917.8,5099)
  Bottom Layer w5: FPC1.25@3538.78,4474.85 3963.65,4474.85 4027.8,4539 v1(4486.8,4539)
LCD0-D19: FPC1.26 | length 2711.2
  内层4 w5: v1(5855.8,4853) 5948.8,4853 v1(5953.8,4858)
  Inner5 w5: v1(4500.8,4523) 4641.8,4523 4693.8,4575 5084.8,4575 5179.8,4670 5815.8,4670 5953.8,4808 v1(5953.8,4858)
  Bottom Layer w5: FPC1.26@3538.78,4455.15 3970.96,4455.15 4037.8,4522 4499.8,4522 v1(4500.8,4523)
LCD0-D20: FPC1.27 | length 3002.4
  Inner5 w5: v1(4515.8,4504) 4645.8,4504 4702.8,4561 5096.8,4561 5188.8,4653 5824.8,4653 5971.8,4800 5971.8,4960 6011.8,5000 6011.8,5012 5971.8,5052 5971.8,5127 5965.8,5133 5923.51,5133 v1(5918.26,5138.25)
  Bottom Layer w5: FPC1.27@3538.78,4435.48 3980.28,4435.48 4048.8,4504 v1(4515.8,4504)
LCD0-D21: FPC1.28 | length 2785.8
  内层4 w5: v1(4531.8,4487) 4568.8,4524 4732.8,4524 4914.8,4706 5562.8,4706 5591.8,4735 5710.8,4735 5901.8,4926 5901.8,4958 5932.8,4989 5932.8,5104.02 v1(5918.26,5118.56)
  Bottom Layer w5: FPC1.28@3538.78,4415.78 3987.59,4415.78 4058.8,4487 v1(4531.8,4487)
LCD0-D22: FPC1.29 | length 887.8
  Bottom Layer w5: FPC1.29@3538.78,4396.1 3997.91,4396.1 4069.8,4468 v1(4396.8,4468)
LCD0-D23: FPC1.30 | length 904.5
  Bottom Layer w5: FPC1.30@3538.78,4376.41 4005.22,4376.41 4078.8,4450 v1(4412.8,4450)
LCD0-DE: FPC1.40 | length 2770.3
  Inner5 w5: v1(4244.8,4323) 4316.8,4323 4364.8,4371 4364.8,4588 4464.8,4688 5020.8,4688 5122.8,4790 5749.8,4790 5856.8,4897 v1(5856.8,4925)
  Bottom Layer w5: FPC1.40@3538.78,4179.56 3595.37,4179.56 3680.8,4265 4086.8,4265 4144.8,4323 v1(4244.8,4323)
LCD0-HSYNC: FPC1.42 | length 3297
  Inner5 w5: v1(4205.8,4288) 4237.8,4288 4257.8,4308 4329.8,4308 4379.8,4358 4379.8,4477 4391.8,4489 4501.8,4489 4521.8,4469 4541.8,4469 4559.8,4487 4654.8,4487 4712.8,4545 5105.8,4545 5196.8,4636 5833.8,4636 5985.8,4788 5985.8,4950 6023.8,4988 6023.8,5023 5982.13,5064.68 5982.13,5131.68 5970.8,5143 5938.8,5143 5927.8,5154 5893.96,5154 v1(5878.89,5138.93)
  Bottom Layer w5: FPC1.42@3538.78,4140.19 3603,4140.19 3698.8,4236 4110.8,4236 4162.8,4288 v1(4205.8,4288)
LCD0-PWM: FPC1.32 | length 2902.1
  内层2 w5: v1(4428.8,4431) 4428.8,4468 4411.8,4485 4411.8,4721 4545.8,4855 4746.8,4855 4765.8,4836 4765.8,4796 4809.8,4752 4897.8,4752 4934.8,4789 4954.8,4789 4996.8,4747 5419.8,4747 5527.8,4855 5715.8,4855 5807.8,4947 v1(5850.8,4947)
  Bottom Layer w5: FPC1.32@3538.78,4337.05 3582.85,4337.05 3604.8,4359 4013.8,4359 4085.8,4431 v1(4428.8,4431)
LCD0-RST: FPC1.33 | length 2864.5
  内层2 w5: v1(4443.8,4414) 4443.8,4476 4427.8,4492 4427.8,4716 4552.8,4841 4738.8,4841 4750.8,4829 4750.8,4792 4811.8,4731 5426.8,4731 5536.8,4841 5723.8,4841 5813.8,4931 v1(5836.8,4931)
  Bottom Layer w5: FPC1.33@3538.78,4317.36 3589.17,4317.36 3613.8,4342 4024.8,4342 4096.8,4414 v1(4443.8,4414)
LCD0-VSYNC: FPC1.41 | length 3162.7
  内层2 w5: v1(4224.8,4305) 4248.8,4305 4300.8,4357 4325.8,4357 4375.8,4407 4375.8,4482 4393.8,4500 4393.8,4728 4534.8,4869 4758.8,4869 4796.8,4831 4835.8,4831 4849.8,4817 4849.8,4797 4864.8,4782 4905.8,4782 4926.8,4803 4963.8,4803 5000.8,4766 5415.8,4766 5518.8,4869 5709.8,4869 5796.8,4956 5796.8,4993 5814.8,5011 5814.8,5139 5829.8,5154 5844.14,5154 5855.8,5142.33 5855.8,5129 5865.56,5119.25 v1(5878.89,5119.25)
  Bottom Layer w5: FPC1.41@3538.78,4159.89 3597.69,4159.89 3688.8,4251 4099.8,4251 4153.8,4305 v1(4224.8,4305)
LEDC:  | length 4297.1
  内层2 w3: v2(3424.8,4207) 3542.8,4089 4670.8,4089 4851.8,4270 5293.8,4270 5339.8,4316 5570.8,4316 5669.8,4217 5757.8,4217 5813.8,4273 6045.8,4273 6069.8,4249 6255.8,4249 6397.8,4391 6397.8,4453 6537.8,4593 6537.8,5353 v2(6517.8,5373)
MCSI0-CKN: FPC2.12 | length 1527.6
  Bottom Layer w4: v2(6136.8,5525) 6136.8,5536 6144.15,5543.34 6443.46,5543.34 6589.8,5397 6589.8,5035 6641.8,4983 6641.8,4869 6707.86,4802.94 6885.02,4802.94 6890.02,4797.94 6900.02,4797.94 6905.02,4802.94 6915.02,4802.94 6920.02,4797.94 6930.02,4797.94 6935.02,4802.94 6945.02,4802.94 6950.02,4797.94 6960.02,4797.94 6965.02,4802.94 6975.02,4802.94 6980.02,4797.94 6990.02,4797.94 6995.02,4802.94 7014.37,4802.94 7020.21,4797.1 FPC2.12@7045.83,4797.1
MCSI0-CKP: FPC2.13 | length 1513.9
  Bottom Layer w4: v2(6119.8,5543) 6132.49,5543 6140.83,5551.34 6446.46,5551.34 6597.8,5400 6597.8,5039 6650.8,4986 6650.8,4877 6716.86,4810.94 7014.37,4810.94 7020.21,4816.78 FPC2.13@7045.83,4816.78
MCSI0-D0N: FPC2.6 | length 1203.5
  Bottom Layer w4: v2(6454.8,5393) 6454.8,5382 6475.8,5361 6475.8,5004 6554.8,4925 6554.8,4780.69 6650.49,4685 6890.54,4685 6895.54,4680 6905.54,4680 6910.54,4685 6920.54,4685 6925.54,4680 6935.54,4680 6940.54,4685 6950.54,4685 6955.54,4680 6965.54,4680 6970.54,4685 6980.54,4685 6985.54,4680 6995.54,4680 7000.54,4685 7016.8,4685 7020.8,4681 7043.82,4681 FPC2.6@7045.83,4678.99
MCSI0-D0P: FPC2.7 | length 1167.9
  Bottom Layer w4: v2(6475.8,5392) 6475.8,5375 6484.8,5366 6484.8,5006 6562.8,4928 6562.8,4784 6654.8,4692 7017.8,4692 7024.48,4698.68 FPC2.7@7045.83,4698.68
MCSI0-D1N: FPC2.9 | length 1565
  Bottom Layer w4: v2(6159.8,5502) 6161.48,5500.32 6428.48,5500.32 6540.85,5387.95 6540.85,5011.95 6597.8,4955 6597.8,4814.53 6668.44,4743.89 6693.89,4743.89 6701.13,4736.65 6708.89,4736.65 6716.13,4743.89 6723.89,4743.89 6731.13,4736.65 6738.89,4736.65 6746.13,4743.89 6753.89,4743.89 6761.13,4736.65 6768.89,4736.65 6776.13,4743.89 6783.89,4743.89 6791.13,4736.65 6798.89,4736.65 6806.13,4743.89 6813.89,4743.89 6821.13,4736.65 6828.89,4736.65 6836.13,4743.89 6843.89,4743.89 6851.13,4736.65 6858.89,4736.65 6866.13,4743.89 6873.89,4743.89 6881.13,4736.65 6888.89,4736.65 6896.13,4743.89 6903.89,4743.89 6911.13,4736.65 6918.89,4736.65 6926.13,4743.89 6933.89,4743.89 6941.13,4736.65 6948.89,4736.65 6956.13,4743.89 6963.89,4743.89 6971.13,4736.65 6978.89,4736.65 6986.13,4743.89 7014.36,4743.89 7020.21,4738.05 FPC2.9@7045.83,4738.05
MCSI0-D1P: FPC2.10 | length 1687.3
  Bottom Layer w4: v2(5998.8,5473) 6108.8,5473 6151.15,5515.35 6167.45,5515.35 6174.48,5508.32 6434.48,5508.32 6548.85,5393.95 6548.85,5014.95 6605.8,4958 6605.8,4817.84 6671.75,4751.89 7014.36,4751.89 7020.21,4757.73 FPC2.10@7045.83,4757.73
MCSI0-D2N: FPC2.15 | length 1578.9
  Inner5 w4: v1(5957,5472.9) 5979.56,5450.34 6485.15,5450.34 6602.8,5332.69 6602.8,4940.69 6681.49,4862 6853.95,4862 6859.95,4856 v2(6869.8,4856)
  Bottom Layer w4: v2(6869.8,4856) 6875.8,4862 7014.36,4862 7020.21,4856.15 FPC2.15@7045.83,4856.15
MCSI0-D2P: FPC2.16 | length 1580.2
  Inner5 w4: v1(5977.8,5473) 5977.8,5465 5984.46,5458.34 6010.47,5458.34 6015.47,5463.34 6025.47,5463.34 6030.47,5458.34 6040.47,5458.34 6045.47,5463.34 6055.47,5463.34 6060.47,5458.34 6070.47,5458.34 6075.47,5463.34 6085.47,5463.34 6090.47,5458.34 6100.47,5458.34 6105.47,5463.34 6115.47,5463.34 6120.47,5458.34 6130.47,5458.34 6135.47,5463.34 6145.47,5463.34 6150.47,5458.34 6488.46,5458.34 6610.8,5336 6610.8,4944 6684.8,4870 6853.95,4870 6859.95,4876 v2(6869.8,4876)
  Bottom Layer w4: v2(6869.8,4876) 6875.8,4870 7014.36,4870 7020.21,4875.85 FPC2.16@7045.83,4875.85
MCSI0-D3N: FPC2.18 | length 1599.4
  Inner5 w4: v1(5976.8,5513) 5983.8,5506 5983.8,5498.1 5993.25,5488.66 6021.46,5488.66 6094.8,5562 6181.8,5562 6239.8,5504 6509.8,5504 6656.8,5357 6656.8,4974.69 6711.19,4920.3 6985.36,4920.3 6991.66,4914 v2(7001.8,4914)
  Bottom Layer w4: v2(7001.8,4914) 7011.65,4914 7017.96,4920.3 FPC2.18@7036.14,4920.3
MCSI0-D3P: FPC2.19 | length 1596.8
  Inner5 w4: v1(5996.8,5513) 5990.8,5507 5990.8,5501 5996.15,5495.66 6017.15,5495.66 6019.82,5498.33 6019.82,5506.01 6026.58,5512.78 6034.27,5512.78 6041.03,5519.54 6041.03,5527.23 6047.79,5533.99 6055.48,5533.99 6091.49,5570 6185.12,5570 6242.12,5513 6512.12,5513 6664.8,5360.31 6664.8,4978 6714.5,4928.3 6985.36,4928.3 6991.66,4934.61 v2(7001.51,4934.61)
  Bottom Layer w4: v2(7001.51,4934.61) 7011.65,4934.61 7017.96,4928.3 7036.14,4928.3
MCSI0-MCLK: FPC2.24 | length 1418.8
  Bottom Layer w6: v2(6062.8,5564) 6078.8,5580 6465.8,5580 6632.8,5413 6632.8,5067 6663.7,5036.11 7043.05,5036.11 FPC2.24@7045.83,5033.32
MCSI0-PWDN: FPC2.28 | length 1236.4
  Bottom Layer w4: v2(6324.8,5620) 6309.8,5605 6293.8,5605 6283.8,5615 6283.8,5629 6302.8,5648 6360.8,5648 6375.8,5633 6478.8,5633 6686.8,5425 6686.8,5132 6715.8,5103 7017.8,5103 7026.87,5112.06 FPC2.28@7045.83,5112.06
MCSI0-RSTN: FPC2.27 | length 1148.9
  Bottom Layer w4: v2(6301.8,5620) 6318.8,5637 6353.8,5637 6370.8,5620 6475.8,5620 6675.8,5420 6675.8,5126 6709.43,5092.38 FPC2.27@7045.83,5092.38
MCSI0-SCK: FPC2.21 R127.2 | length 1542.8
  Inner5 w4: v1(5977,5551.64) 5977,5545.8 5986.8,5536 6007.8,5536 6075.8,5604 6211.8,5604 6270.8,5545 6534.8,5545 6702.8,5377 6702.8,5174 6849.8,5027 6941.8,5027 6986.8,4982 v2(6987.8,4982)
  Bottom Layer w4: v2(6987.8,4982) 6995.54,4974.27 FPC2.21@7045.83,4974.27
  Bottom Layer w6: v1(5977,5551.64) 5977,5557.2 5985.8,5566 6018.29,5566 R127.2@6022.29,5562
MCSI0-SDA: FPC2.22 R128.2 | length 1482.4
  Inner5 w4: v1(5996.69,5551.64) 6006.44,5551.64 6069.8,5615 6219.8,5615 6277.8,5557 6539.8,5557 6713.8,5383 6713.8,5180 6856.8,5037 6949.8,5037 6981.8,5005 v2(6988.8,5005)
  Bottom Layer w4: v2(6988.8,5005) 6999.85,4993.95 FPC2.22@7045.83,4993.95
  Bottom Layer w6: v1(5996.69,5551.64) 6006.17,5551.64 6018.8,5539 R128.2@6022.29,5539
MCSI0-USER: FPC2.26 | length 1095.7
  Bottom Layer w4: v2(6348.8,5618) 6354.8,5618 6364.8,5608 6472.8,5608 6663.8,5417 6663.8,5122 6706.8,5079 7020.8,5079 7027.11,5072.69 FPC2.26@7045.83,5072.69
MICIN3N: C241.1 | length 823.1
  内层2 w5: v1(5548.8,5710) 5548.8,5725.71 5552.3,5729.21 5552.3,5740.01 5584.29,5772 5769.8,5772 5869.8,5872 5919.8,5872 v2(5924.8,5877)
  Bottom Layer w5: v2(5924.8,5877) 5931.8,5877 5990.8,5936 6024.8,5936 6093.8,6005 6093.8,6076.27 6080.57,6089.51 6080.57,6120.23 6073.57,6127.23 C241.1@6073.57,6136.99
MICIN3P: C238.1 | length 820.7
  内层2 w5: v1(5569.8,5712.84) 5569.8,5725.71 5566.3,5729.21 5566.3,5734.21 5590.09,5758 5775.6,5758 5877.6,5860 5916.8,5860 v2(5924.8,5852)
  Bottom Layer w5: v2(5924.8,5852) 5995.8,5923 6024.53,5923 6102.8,6001.27 6102.8,6080 6089.57,6093.24 6089.57,6120.23 6096.57,6127.23 C238.1@6096.57,6136.99
PE0:  | length 2254.2
  Inner5 w4: 4132.8,6343 4183.8,6292 4183.8,6209 4238.8,6154 4349.8,6154 4418.8,6085 5410.8,6085 5593.8,5902 5668.8,5902 5838.8,5732 5838.8,5708 5901.8,5645 5963.8,5645 5971.18,5637.63 5971.18,5609.63 5988.8,5592 v1(5996.8,5592)
PE1:  | length 1773.3
  VCC w4: 4632.8,6243 4633.8,6243 4797.8,6079 5388.8,6079 5567.8,5900 5734.8,5900 5872.8,5762 5927.8,5762 5966.8,5723 6121.8,5723 6125.8,5727 6167.8,5727 v1(6182.8,5712)
PE2:  | length 2053.7
  Inner5 w4: 4232.8,6243 4307.8,6168 4354.8,6168 4423.8,6099 5418.8,6099 5602.8,5915 5674.8,5915 5851.8,5738 5851.8,5714 5907.8,5658 5968.8,5658 5982.8,5644 5982.8,5620.24 5990.41,5612.64 5996.06,5612.64 v1(5997.01,5611.69)
PE3:  | length 2140.2
  Inner5 w4: 4332.8,6343 4307.37,6317.57 4301.37,6317.57 4284.8,6301 4284.8,6206 4307.8,6183 4360.8,6183 4431.8,6112 5426.8,6112 5610.8,5928 5684.8,5928 5864.8,5748 5864.8,5717 5910.8,5671 5976.8,5671 5997.01,5650.8 v1(5997.01,5631.38)
PE4:  | length 2038.7
  Inner5 w4: 4332.8,6243 4332.8,6234 4441.8,6125 5433.8,6125 5586.8,5972 5664.8,5972 5908.8,5728 6097.8,5728 v1(6136.8,5767)
PE5:  | length 1915.7
  VCC w4: 4632.8,6343 4632.8,6340 4582.8,6290 4582.8,6215 4731.8,6066 5380.8,6066 5559.8,5887 5727.8,5887 5865.8,5749 5920.8,5749 5959.8,5710 6137.8,5710 v1(6139.8,5712)
PE6:  | length 1863.6
  VCC w4: 4532.8,6243 4532.8,6241 4720.8,6053 5375.8,6053 5556.8,5872 5721.8,5872 5855.8,5738 5913.8,5738 5954.68,5697.12 6148.92,5697.12 6161.8,5710 v1(6161.8,5712)
PE7:  | length 1864.6
  VCC w4: 4732.8,6343 4731.8,6343 4684.8,6296 4684.8,6213 4805.8,6092 5394.8,6092 5573.8,5913 5741.8,5913 5880.8,5774 5934.8,5774 5973.8,5735 6117.8,5735 6119.8,5737 6160.8,5737 6180.8,5757 v1(6180.8,5768)
PE8:  | length 1650.3
  VCC w4: 4732.8,6243 4732.8,6225 4849.8,6108 5400.8,6108 5580.8,5928 5746.8,5928 5888.8,5786 5939.8,5786 5978.8,5747 6138.8,5747 v1(6158.8,5767)
PE9:  | length 2095.1
  Inner5 w4: 4432.8,6343 4432.8,6341 4383.8,6292 4383.8,6203 4448.8,6138 5441.8,6138 5590.8,5989 5672.8,5989 5922.8,5739 6086.8,5739 v1(6114.8,5767)
PE10:  | length 1399.8
  Inner5 w4: 4932.8,6243 5024.8,6151 5479.8,6151 5607.8,6023 5663.8,6023 5692.8,5994 5735.8,5994 5743.8,5986 5743.8,5939 5932.8,5750 6076.8,5750 v1(6093.8,5767)
PE11:  | length 2336
  Inner5 w4: 3932.8,6243 4050.8,6125 4337.8,6125 4403.8,6059 5391.8,6059 5573.8,5877 5653.8,5877 5705.8,5825 5705.8,5758 5737.8,5726 5785.8,5726 5894.8,5617 5894.8,5574 5916.48,5552.32 v1(5918.26,5552.32)
PE12:  | length 1640.4
  VCC w4: 4832.8,6343 4783.8,6294 4783.8,6192 4851.8,6124 5406.8,6124 5557.8,5973 5642.8,5973 5672.8,5943 5753.8,5943 5896.8,5800 5946.8,5800 5987.8,5759 6060.8,5759 v1(6069.8,5768)
PE13:  | length 2146.6
  Inner5 w4: 4132.8,6243 4132.8,6238 4230.8,6140 4343.8,6140 4411.8,6072 5399.8,6072 5583.8,5888 5661.8,5888 5717.8,5832 5717.8,5766 5744.8,5739 5789.8,5739 5899.8,5629 5923.8,5629 5936.8,5616 5936.8,5598 5942.8,5592 v1(5957.63,5592.01)
PE14:  | length 2409.8
  Inner5 w4: 3832.8,6243 3965.8,6110 4330.8,6110 4394.8,6046 5385.21,6046 5566.21,5865 5646.8,5865 5693.8,5818 5693.8,5750 5729.8,5714 5781.8,5714 5853.8,5642 5853.8,5599 5863.8,5589 5863.8,5567.41 v1(5878.89,5552.32)
PE15:  | length 2465.9
  Inner5 w4: 3732.8,6243 3732.8,6230 3866.8,6096 4322.8,6096 4384.8,6034 5094.8,6034 5275.8,5853 5513.8,5853 5537.8,5829 5594.8,5829 5743.8,5680 5796.8,5680 5839.8,5637 5839.8,5597 5853.8,5583 5853.8,5560 5846.12,5552.32 v1(5839.52,5552.32)
PGAOUT0: R26.1 | length 235.9
  Bottom Layer w3: v1(5760.8,5533) 5784.8,5557
  Bottom Layer w6: R26.1@5711.8,5662.51 5711.8,5674 5717.8,5680 5769.8,5680 5785.78,5664.02 5785.78,5557.98 5784.8,5557
PGAOUT1: R27.1 | length 155.9
  Bottom Layer w6: v1(5740.78,5493.27) 5740.78,5621 5753.31,5633.53 R27.1@5753.31,5644
PHYRSTB0:  | length 1754.8
  内层2 w4: v1(5996.69,5395.16) 6050.97,5395.16 6079.8,5424 6172.8,5424 6187.8,5439 6259.8,5439 6269.8,5429 6331.8,5429 6449.8,5311 6449.8,4620 6218.8,4389 6218.8,4312 6194.8,4288 6156.8,4288 6156.7,4287.9 v1(6093,4287.9)
PHYRSTB1:  | length 1313.2
  内层2 w4: v1(6811.8,4279) 6837.8,4279 6870.8,4312 6870.8,4346 6864.8,4352 6864.8,4371 6875.8,4382 6888.8,4382 6924.8,4418 6924.8,4454 6867.8,4511 6867.8,4570 6836.8,4601 6836.8,5467 v1(6846.8,5477)
PMU-SCK:  | length 1914.9
  Bottom Layer w4: v1(3806.8,5244) 3791.8,5229 3594.8,5229 3550.8,5273 3550.8,5359 3524.8,5385 v1(3524.8,5392) 3533.8,5401 3544.42,5401 3568.42,5377 3758.8,5377 3812.8,5431 3812.8,5589 3888.8,5665 4733.8,5665 4760.8,5692 v2(4792.8,5692)
PMU-SDA:  | length 1977.8
  Bottom Layer w4: v1(3827.8,5244) 3803.8,5220 3588.8,5220 3540.8,5268 3540.8,5356 3510.8,5386 3510.8,5400 v1(3523.8,5413) 3546.8,5413 3571.8,5388 3753.8,5388 3803.8,5438 3803.8,5627 3853.8,5677 4725.8,5677 4755.8,5707 v2(4768.8,5707)
PS: C26.1 C29.1 C30.1 C46.1 C56.2 C79.2 C82.2 C285.2 C286.2 C287.2 | length 436.5
  Bottom Layer w4: C46.1@3746.3,5429 v1(3755.8,5429)
  Bottom Layer w15: v1(3698.8,5410) 3702.8,5406 C30.1@3723.3,5406 ; v1(3752.8,5508) 3758.8,5513.99 C82.2@3758.8,5524 ; v1(3752.8,5586) 3758.8,5580.01 C56.2@3758.8,5559
  Bottom Layer w20: 3553.8,5522 v1(3572.8,5522) ; v1(3572.8,5460.49) 3563.29,5470 C79.2@3549.81,5470 ; v1(3572.8,5479) 3558.81,5479 C79.2@3549.81,5470 ; C26.1@3577.8,5578.01 3577.8,5546 v1(3572.8,5541) 3551.09,5541 3549.81,5539.72 C29.1@3549.81,5504.72 C79.2@3549.81,5470 ; C286.2@3651.8,5646.47 3667.8,5630.47 v1(3667.8,5592) ; v1(3688.8,5592) 3688.8,5636.47 C285.2@3698.8,5646.47 ; v1(3752.8,5508) 3752.8,5485.47 C287.2@3756.8,5481.47
  other v1: 4037.8,5106 4016.8,5199 3982.64,5235.49 3675.8,5634
PWRON:  | length 605.7
  内层4 w6: v1(3662.8,5409) 3678.8,5393 3748.8,5393 3754.8,5387 4236.8,5387 v2(4252.8,5371)
RGMII0-CLKIN:  | length 1611
  内层2 w4: v1(5815.8,4350.9) 5822.7,4344 6144.8,4344 6168.8,4368 6168.8,4405 6412.8,4649 6412.8,5291 6307.8,5396 6240.8,5396 v1(6236.8,5400)
RGMII0-MDC:  | length 1385.1
  内层2 w4: v1(6172.8,4306) 6184.8,4318 6184.8,4400 6424.8,4640 6424.8,5297 6315.8,5406 6253.8,5406 6244.8,5415 6203.8,5415 v1(6189.8,5401)
RGMII0-MDIO:  | length 1414.3
  内层2 w4: v1(6167.8,5401) 6192.8,5426 6253.8,5426 6262.8,5417 6323.8,5417 6436.8,5304 6436.8,4629 6199.8,4392 6199.8,4322 v1(6202.8,4319)
RGMII0-RXCK:  | length 1521.6
  内层2 w4: v1(5927.8,4513.49) 5936.8,4504.49 5936.8,4452 5974.8,4414 6097.8,4414 6363.8,4680 6363.8,5268 6280.8,5351 6154.8,5351 v1(6103.8,5402)
RGMII0-RXCTL:  | length 1561.8
  内层2 w4: v1(5949.8,4513.49) 5949.8,4456 5978.8,4427 6088.8,4427 6349.8,4688 6349.8,5266 6278.8,5337 6146.8,5337 6108.8,5375 6015.92,5375 v1(5996.69,5355.78)
RGMII0-RXD0:  | length 1532
  内层2 w4: v1(5972.8,4513.49) 5972.8,4508 5963.8,4499 5963.8,4459 5984.8,4438 6078.8,4438 6336.8,4696 6336.8,5260 6271.8,5325 6140.8,5325 6104.8,5361 6022.8,5361 6002.8,5341 5982.91,5341 5977.01,5346.9 v1(5977.01,5355.78)
RGMII0-RXD1:  | length 1489.5
  内层2 w4: v1(5957.32,5355.78) 5957.32,5350.48 5976.17,5331.63 6012.43,5331.63 6028.8,5348 6099.8,5348 6135.8,5312 6265.8,5312 6323.8,5254 6323.8,4705 6067.8,4449 5993.8,4449 5977.8,4465 5977.8,4494.02 v1(5997.27,4513.49)
RGMII0-RXD2:  | length 1812.8
  内层4 w4: v1(5996.69,5434.53) 6001.27,5434.53 6078.8,5357 6400.8,5357 6493.8,5264 6493.8,4594 6344.8,4445 6068.8,4445 6020.8,4493 v1(6020.8,4513.49)
RGMII0-RXD3:  | length 1782.9
  内层4 w4: v1(5977,5434.53) 5992.53,5419 6000.8,5419 6073.8,5346 6393.8,5346 6482.8,5257 6482.8,4598 6340.8,4456 6074.8,4456 6035.8,4495 6035.8,4503.49 v1(6045.8,4513.49)
RGMII0-TXCK:  | length 1629.3
  内层2 w3: v1(5936.8,5435) 5950.8,5449 6001.8,5449 6015.8,5435 6035.8,5435 6039.8,5439
  内层2 w4: 6039.8,5439 6057.8,5457 6152.8,5457 6172.8,5477 6280.8,5477 6290.8,5467 6352.8,5467 6488.8,5331 6488.8,4593 6346.8,4451 v1(6346.8,4402)
RGMII0-TXCTL:  | length 1589.2
  内层2 w4: v1(5957.33,5434.53) 5973.85,5418 6038.8,5418 6065.8,5445 6157.8,5445 6176.8,5464 6272.8,5464 6282.8,5454 6345.8,5454 6475.8,5324 6475.8,4603 6331.8,4459 6331.8,4411 v1(6321.8,4401)
RGMII0-TXD0:  | length 1565.8
  内层2 w4: v1(5977.01,5395.16) 5990.84,5409 6047.8,5409 6073.8,5435 6163.8,5435 6180.8,5452 6265.8,5452 6275.8,5442 6338.8,5442 6462.8,5318 6462.8,4611 6317.8,4466 6317.8,4420 6298.8,4401 v1(6298.8,4385)
RGMII0-TXD1:  | length 1330.3
  内层2 w4: v1(6083.8,4370) 6093.8,4360 6142.8,4360 6154.8,4372 6154.8,4410 6401.8,4657 6401.8,5283 6299.8,5385 6229.8,5385 v1(6213.8,5401)
RGMII0-TXD2:  | length 1307
  内层2 w4: v1(6115.8,4379) 6124.8,4388 6124.8,4420 6376.8,4672 6376.8,5272 6285.8,5363 6163.8,5363 v1(6124.8,5402)
RGMII0-TXD3:  | length 1297.2
  内层2 w4: v1(6138.8,4379) 6138.8,4414 6389.8,4665 6389.8,5276 6291.8,5374 6173.8,5374 v1(6145.8,5402)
